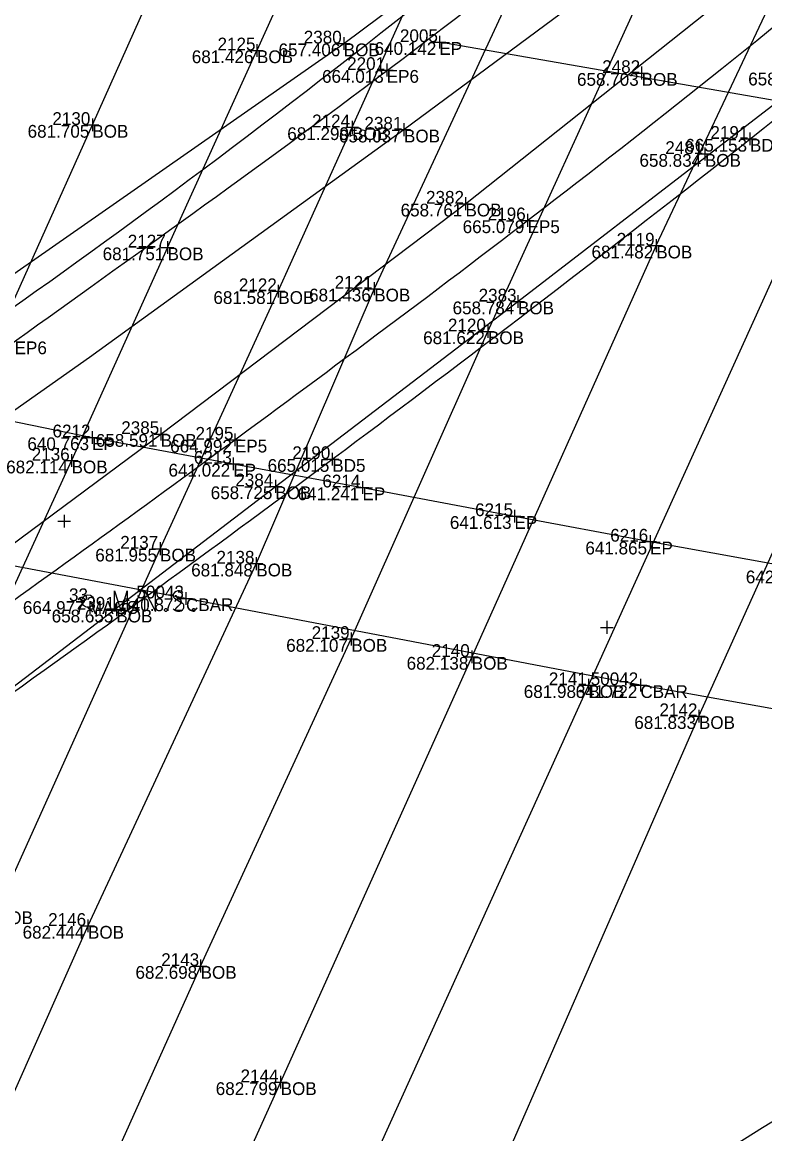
# Model space of a CAD drawing. Extents: x 2197382 to 2204062, y 634117 to 636522.
# Drawn here: x 2202695.7 to 2202753.9, y 635314.3 to 635401.4 of the extents above; entities that cross this region are included whole.
import ezdxf

# ---------------------------------------------------------------- set-up
doc = ezdxf.new("R2010")
doc.units = 0
for name, color, linetype in [('_CIVIL_CONSTRUCTION', 7, 'Continuous'), ('BR_X_SV_Bottom_of_Beam', 7, 'Continuous'), ('BR_X_SV_Bottom_of_Beam_Text', 7, 'Continuous'), ('BR_X_SV_Deck_Top', 7, 'Continuous'), ('BR_X_SV_Deck_Top_Text', 7, 'Continuous'), ('GE_P_Alignment_100_Distances', 7, 'Continuous'), ('RD_X_Concrete_Barrier', 7, 'Continuous'), ('SH_Border', 7, 'Continuous'), ('SH_Cut_Line', 7, 'Continuous'), ('SH_Data', 7, 'Continuous'), ('SV_P_Control_Cells_Set', 7, 'Continuous')]:
    doc.layers.add(name, color=color, linetype=linetype)

msp = doc.modelspace()

# ---------------------------------------------------------------- linework, layer by layer
at = {"layer": '_CIVIL_CONSTRUCTION'}
for p, q in [((2202720.902, 635400.269), (2202720.902, 635399.269)), ((2202728.393, 635400.378), (2202728.393, 635399.378)), ((2202713.604, 635399.229), (2202714.604, 635399.229)), ((2202714.104, 635399.729), (2202714.104, 635398.729)), ((2202714.104, 635399.229), (2202714.104, 635399.229)), ((2202720.402, 635399.769), (2202721.402, 635399.769)), ((2202720.902, 635399.769), (2202720.902, 635399.769)), ((2202727.893, 635399.878), (2202728.893, 635399.878)), ((2202728.393, 635399.878), (2202728.393, 635399.878)), ((2202723.767, 635397.691), (2202724.767, 635397.691)), ((2202724.267, 635398.191), (2202724.267, 635397.191)), ((2202724.267, 635397.691), (2202724.267, 635397.691)), ((2202743.737, 635397.455), (2202744.737, 635397.455)), ((2202744.237, 635397.955), (2202744.237, 635396.955)), ((2202744.237, 635397.455), (2202744.237, 635397.455)), ((2202701.21, 635393.885), (2202701.21, 635392.885)), ((2202700.71, 635393.385), (2202701.71, 635393.385)), ((2202701.21, 635393.385), (2202701.21, 635393.385)), ((2202721.062, 635393.2), (2202722.062, 635393.2)), ((2202721.562, 635393.7), (2202721.562, 635392.7)), ((2202721.562, 635393.2), (2202721.562, 635393.2)), ((2202725.122, 635393.015), (2202726.122, 635393.015)), ((2202725.622, 635393.515), (2202725.622, 635392.515)), ((2202725.622, 635393.015), (2202725.622, 635393.015)), ((2202752.224, 635392.292), (2202753.224, 635392.292)), ((2202752.724, 635392.792), (2202752.724, 635391.792)), ((2202752.724, 635392.292), (2202752.724, 635392.292)), ((2202749.19, 635391.608), (2202749.19, 635390.608)), ((2202748.69, 635391.108), (2202749.69, 635391.108)), ((2202749.19, 635391.108), (2202749.19, 635391.108)), ((2202729.939, 635387.213), (2202730.939, 635387.213)), ((2202730.439, 635387.713), (2202730.439, 635386.713)), ((2202730.439, 635387.213), (2202730.439, 635387.213)), ((2202735.303, 635386.407), (2202735.303, 635385.407)), ((2202734.803, 635385.907), (2202735.803, 635385.907)), ((2202735.303, 635385.907), (2202735.303, 635385.907)), ((2202707.099, 635384.278), (2202707.099, 635383.278)), ((2202745.383, 635384.423), (2202745.383, 635383.423)), ((2202706.599, 635383.778), (2202707.599, 635383.778)), ((2202707.099, 635383.778), (2202707.099, 635383.778)), ((2202744.883, 635383.923), (2202745.883, 635383.923)), ((2202745.383, 635383.923), (2202745.383, 635383.923)), ((2202715.777, 635380.853), (2202715.777, 635379.853)), ((2202723.291, 635381.051), (2202723.291, 635380.051)), ((2202715.277, 635380.353), (2202716.277, 635380.353)), ((2202715.777, 635380.353), (2202715.777, 635380.353)), ((2202722.791, 635380.551), (2202723.791, 635380.551)), ((2202723.291, 635380.551), (2202723.291, 635380.551)), ((2202734.551, 635380.043), (2202734.551, 635379.043)), ((2202734.051, 635379.543), (2202735.051, 635379.543)), ((2202734.551, 635379.543), (2202734.551, 635379.543)), ((2202732.197, 635377.703), (2202732.197, 635376.703)), ((2202731.697, 635377.203), (2202732.697, 635377.203)), ((2202732.197, 635377.203), (2202732.197, 635377.203)), ((2202706.563, 635369.657), (2202706.563, 635368.657)), ((2202700.684, 635368.894), (2202701.684, 635368.894)), ((2202701.184, 635369.394), (2202701.184, 635368.394)), ((2202701.184, 635368.894), (2202701.184, 635368.894)), ((2202706.063, 635369.157), (2202707.063, 635369.157)), ((2202706.563, 635369.157), (2202706.563, 635369.157)), ((2202711.879, 635368.711), (2202712.879, 635368.711)), ((2202712.379, 635369.211), (2202712.379, 635368.211)), ((2202712.379, 635368.711), (2202712.379, 635368.711)), ((2202699.084, 635367.074), (2202700.084, 635367.074)), ((2202699.584, 635367.574), (2202699.584, 635366.574)), ((2202699.584, 635367.074), (2202699.584, 635367.074)), ((2202712.248, 635367.324), (2202712.248, 635366.324)), ((2202719.509, 635367.194), (2202720.509, 635367.194)), ((2202720.009, 635367.694), (2202720.009, 635366.694)), ((2202720.009, 635367.194), (2202720.009, 635367.194)), ((2202711.748, 635366.824), (2202712.748, 635366.824)), ((2202712.248, 635366.824), (2202712.248, 635366.824)), ((2202715.55, 635365.554), (2202715.55, 635364.554)), ((2202722.37, 635365.473), (2202722.37, 635364.473)), ((2202715.05, 635365.054), (2202716.05, 635365.054)), ((2202715.55, 635365.054), (2202715.55, 635365.054)), ((2202721.87, 635364.973), (2202722.87, 635364.973)), ((2202722.37, 635364.973), (2202722.37, 635364.973)), ((2202699.008, 635362.818), (2202699.008, 635361.818)), ((2202733.779, 635362.722), (2202734.779, 635362.722)), ((2202734.279, 635363.222), (2202734.279, 635362.222)), ((2202734.279, 635362.722), (2202734.279, 635362.722)), ((2202698.508, 635362.318), (2202699.508, 635362.318)), ((2202699.008, 635362.318), (2202699.008, 635362.318)), ((2202744.899, 635361.221), (2202744.899, 635360.221)), ((2202706.01, 635360.169), (2202707.01, 635360.169)), ((2202706.51, 635360.669), (2202706.51, 635359.669)), ((2202706.51, 635360.169), (2202706.51, 635360.169)), ((2202744.399, 635360.721), (2202745.399, 635360.721)), ((2202744.899, 635360.721), (2202744.899, 635360.721)), ((2202713.553, 635358.998), (2202714.553, 635358.998)), ((2202714.053, 635359.498), (2202714.053, 635358.498)), ((2202714.053, 635358.998), (2202714.053, 635358.998)), ((2202708.544, 635356.774), (2202708.544, 635355.774)), ((2202703.092, 635355.89), (2202703.092, 635354.89)), ((2202708.044, 635356.274), (2202709.044, 635356.274)), ((2202708.544, 635356.274), (2202708.544, 635356.274)), ((2202702.592, 635355.39), (2202703.592, 635355.39)), ((2202703.092, 635355.39), (2202703.092, 635355.39)), ((2202741.009, 635354.004), (2202742.009, 635354.004)), ((2202741.509, 635354.504), (2202741.509, 635353.504)), ((2202741.509, 635354.004), (2202741.509, 635354.004)), ((2202720.992, 635353.092), (2202721.992, 635353.092)), ((2202721.492, 635353.592), (2202721.492, 635352.592)), ((2202721.492, 635353.092), (2202721.492, 635353.092)), ((2202730.929, 635352.186), (2202730.929, 635351.186)), ((2202730.429, 635351.686), (2202731.429, 635351.686)), ((2202730.929, 635351.686), (2202730.929, 635351.686)), ((2202739.569, 635349.468), (2202740.569, 635349.468)), ((2202740.069, 635349.968), (2202740.069, 635348.968)), ((2202740.069, 635349.468), (2202740.069, 635349.468)), ((2202743.64, 635349.469), (2202744.64, 635349.469)), ((2202744.14, 635349.969), (2202744.14, 635348.969)), ((2202744.14, 635349.469), (2202744.14, 635349.469)), ((2202748.226, 635347.039), (2202749.226, 635347.039)), ((2202748.726, 635347.539), (2202748.726, 635346.539)), ((2202748.726, 635347.039), (2202748.726, 635347.039)), ((2202700.37, 635330.601), (2202701.37, 635330.601)), ((2202700.87, 635331.101), (2202700.87, 635330.101)), ((2202700.87, 635330.601), (2202700.87, 635330.601)), ((2202709.688, 635327.957), (2202709.688, 635326.957)), ((2202709.188, 635327.457), (2202710.188, 635327.457)), ((2202709.688, 635327.457), (2202709.688, 635327.457)), ((2202715.46, 635318.345), (2202716.46, 635318.345)), ((2202715.96, 635318.845), (2202715.96, 635317.845)), ((2202715.96, 635318.345), (2202715.96, 635318.345))]:
    msp.add_line(p, q, dxfattribs=at)
at = {"layer": 'BR_X_SV_Bottom_of_Beam'}
for p, q in [((2202729.172, 635432.784), (2202714.104, 635399.229)), ((2202721.562, 635393.2), (2202737.494, 635428.47)), ((2202745.383, 635383.923), (2202761.441, 635418.052)), ((2202732.197, 635377.203), (2202748.335, 635412.641)), ((2202737.812, 635411.851), (2202723.291, 635380.551)), ((2202707.099, 635383.778), (2202714.104, 635399.229)), ((2202748.726, 635347.039), (2202772.072, 635399.002)), ((2202715.777, 635380.353), (2202721.562, 635393.2)), ((2202758.945, 635391.176), (2202740.069, 635349.468)), ((2202707.099, 635383.778), (2202699.584, 635367.074)), ((2202745.383, 635383.923), (2202730.929, 635351.686)), ((2202706.51, 635360.169), (2202715.777, 635380.353)), ((2202723.291, 635380.551), (2202714.053, 635358.998)), ((2202721.492, 635353.092), (2202732.197, 635377.203)), ((2202699.584, 635367.074), (2202684.722, 635334.745)), ((2202693.73, 635331.743), (2202706.51, 635360.169)), ((2202714.053, 635358.998), (2202700.87, 635330.601)), ((2202709.688, 635327.457), (2202721.492, 635353.092)), ((2202730.929, 635351.686), (2202715.96, 635318.345)), ((2202729.105, 635302.144), (2202748.726, 635347.039))]:
    msp.add_line(p, q, dxfattribs=at)
for points in [[(2202550.738, 635261.3), (2202572.992, 635273.891), (2202594.556, 635285.879), (2202604.099, 635291.315), (2202615.232, 635297.565), (2202632.636, 635308.407), (2202649.916, 635319.32), (2202686.545, 635342.9), (2202715.55, 635365.054), (2202734.551, 635379.543), (2202765.2, 635403.192), (2202782.887, 635418.269), (2202797.351, 635430.625), (2202810.639, 635442.162), (2202822.488, 635452.15)], [(2202692.588, 635374.159), (2202701.21, 635393.385), (2202709.973, 635412.997), (2202724.495, 635444.824)], [(2202692.151, 635358.452), (2202706.563, 635369.157), (2202730.439, 635387.213), (2202776.237, 635423.633), (2202788.518, 635433.729)], [(2202513.324, 635270.745), (2202518.461, 635273.222), (2202532.26, 635280.283), (2202548.237, 635288.645), (2202560.651, 635295.117), (2202588.283, 635310.399), (2202608.693, 635322.992), (2202620.515, 635330.213), (2202626.072, 635333.707), (2202636.254, 635340.133), (2202656.933, 635353.888), (2202662.455, 635358.969), (2202720.902, 635399.769), (2202735.154, 635410.438), (2202760.7, 635432.077)], [(2202624.848, 635323.108), (2202626.632, 635325.163), (2202640.898, 635333.252), (2202660.713, 635346.321), (2202681.445, 635361.418), (2202700.993, 635375.17), (2202725.622, 635393.015), (2202741.163, 635404.571), (2202768.027, 635427.422)], [(2202740.069, 635349.468), (2202715.953, 635296.202), (2202694.386, 635248.414), (2202667.266, 635188.144), (2202637.877, 635121.952)], [(2202700.87, 635330.601), (2202688.972, 635303.876), (2202667.875, 635257.009), (2202653.513, 635225.855), (2202612.344, 635134.534)], [(2202709.688, 635327.457), (2202697.509, 635300.34), (2202676.043, 635253.072), (2202658.006, 635212.414), (2202623.889, 635137.034)], [(2202715.96, 635318.345), (2202706.84, 635298.156), (2202685.056, 635250.63), (2202665.977, 635208.006), (2202633.465, 635136.302)]]:
    msp.add_lwpolyline(points, dxfattribs=at)
at = {"layer": 'BR_X_SV_Deck_Top'}
for points in [[(2202430.051, 635233.588), (2202439.74, 635238.507), (2202466.339, 635247.691), (2202507.168, 635268.028), (2202543.723, 635286.397), (2202574.877, 635303.715), (2202604.911, 635320.157), (2202634.127, 635339.4), (2202663.018, 635358.594), (2202692.445, 635376.507), (2202729.246, 635404.451), (2202755.806, 635426.417), (2202769.739, 635438.84)], [(2202458.051, 635216.681), (2202477.116, 635219.979), (2202511.723, 635243.78), (2202554.955, 635262.299), (2202588.014, 635280.674), (2202608.342, 635292.387), (2202640.833, 635312.137), (2202668.147, 635329.948), (2202698.573, 635351.315), (2202722.135, 635368.649), (2202754.604, 635393.426), (2202777.494, 635412.293), (2202789.607, 635422.635)], [(2202895.365, 635391.811), (2202885.347, 635387.334), (2202865.192, 635377.205), (2202839.037, 635363.762), (2202813.103, 635349.723), (2202789.18, 635336.138), (2202762.388, 635320.287), (2202740.668, 635306.565), (2202716.628, 635290.831), (2202693.394, 635275.343), (2202664.567, 635254.787), (2202633.536, 635231.765), (2202595.89, 635201.643), (2202569.397, 635178.622), (2202555.165, 635165.675)], [(2202923.181, 635376.197), (2202906.167, 635369.085), (2202881.487, 635355.934), (2202846.739, 635338.13), (2202819.013, 635322.649), (2202790.142, 635306.09), (2202754.022, 635283.778), (2202709.422, 635255.583), (2202663.285, 635220.884), (2202620.566, 635187.914), (2202595.285, 635167.396), (2202582.509, 635156.81)]]:
    msp.add_open_spline(points, degree=3, dxfattribs=at)
at = {"layer": 'GE_P_Alignment_100_Distances'}
for points in [[(2202975.789, 635361.358), (2202911.398, 635369.868), (2202894.289, 635372.201), (2202871.103, 635375.635), (2202823.555, 635383.286), (2202728.393, 635399.878)], [(2202624.529, 635384.858), (2202633.951, 635382.782), (2202644.483, 635380.376), (2202656.846, 635378.03), (2202666.311, 635376.086), (2202679.647, 635373.315), (2202690.616, 635371.05), (2202701.184, 635368.894), (2202712.248, 635366.824), (2202722.37, 635364.973), (2202734.279, 635362.722), (2202744.899, 635360.721), (2202757.462, 635358.453), (2202767.225, 635356.724), (2202777.62, 635355.092), (2202788.795, 635353.014), (2202801.805, 635351.004), (2202818.285, 635348.253), (2202834.346, 635345.79)]]:
    msp.add_lwpolyline(points, dxfattribs=at)
for points in [[(2202483.163, 635252.761), (2202495.402, 635258.227), (2202515.209, 635267.824), (2202539.505, 635280.183), (2202556.272, 635289.074), (2202570.794, 635297.089), (2202585.76, 635305.335), (2202607.83, 635319.01), (2202630.778, 635332.646), (2202656.431, 635348.815), (2202675.69, 635362.468), (2202698.981, 635379.185), (2202729.904, 635401.353), (2202753.674, 635420.874), (2202767.823, 635433.185)], [(2202457.668, 635223.282), (2202466.48, 635226.872), (2202500.455, 635242.355), (2202539.476, 635261.183), (2202573.06, 635279.52), (2202585.609, 635286.631), (2202599.84, 635294.842), (2202617.618, 635305.231), (2202642.294, 635320.395), (2202667.372, 635336.77), (2202691.723, 635353.633), (2202713.413, 635369.403), (2202739.641, 635388.973), (2202758.657, 635404.276), (2202770.061, 635413.813)], [(2202926.993, 635398.223), (2202911.054, 635391.267), (2202884.78, 635379.221), (2202850.251, 635362.173), (2202828.215, 635350.038), (2202808.09, 635339.198), (2202790.855, 635329.045), (2202764, 635313.325), (2202738.781, 635297.635), (2202713.051, 635280.577), (2202697.019, 635269.602), (2202684.529, 635260.864), (2202668.986, 635249.754), (2202642.65, 635230.806), (2202596.561, 635193.887), (2202560.681, 635163.156), (2202538.312, 635142.813)], [(2202919.499, 635378.368), (2202901.447, 635370.678), (2202875.936, 635356.879), (2202844.592, 635341.598), (2202825.856, 635330.823), (2202809.466, 635322.019), (2202780.051, 635304.409), (2202746.062, 635282.999), (2202707.717, 635258.176), (2202682.244, 635240.209), (2202658.947, 635222.257), (2202614.143, 635189.251), (2202577.354, 635157.516), (2202549.508, 635131.427)]]:
    msp.add_open_spline(points, degree=3, dxfattribs=at)
at = {"layer": 'RD_X_Concrete_Barrier'}
msp.add_lwpolyline([(2202800.07, 635339.72), (2202776.238, 635343.723), (2202744.14, 635349.469), (2202708.544, 635356.274), (2202679.329, 635361.788), (2202653.683, 635367.051)], dxfattribs=at)
at = {"layer": 'SV_P_Control_Cells_Set'}
for points in [[(2202702.958, 635355.258), (2202702.958, 635356.858), (2202703.465, 635355.258), (2202703.95, 635356.858), (2202703.95, 635355.258)], [(2202705.328, 635355.258), (2202705.328, 635356.858), (2202706.155, 635355.258), (2202706.155, 635356.858)], [(2202708.305, 635356.745), (2202708.283, 635356.77), (2202708.249, 635356.795), (2202708.15, 635356.833), (2202708.029, 635356.858), (2202707.941, 635356.858), (2202707.908, 635356.858), (2202707.764, 635356.821), (2202707.643, 635356.745), (2202707.566, 635356.644), (2202707.544, 635356.543), (2202707.544, 635356.468), (2202707.566, 635356.367), (2202707.654, 635356.279), (2202708.261, 635355.901), (2202708.316, 635355.851), (2202708.338, 635355.8), (2202708.36, 635355.725), (2202708.36, 635355.649), (2202708.349, 635355.573), (2202708.338, 635355.523), (2202708.316, 635355.46), (2202708.294, 635355.41), (2202708.271, 635355.372), (2202708.238, 635355.334), (2202708.205, 635355.309), (2202708.161, 635355.284), (2202708.128, 635355.271), (2202708.029, 635355.258), (2202707.875, 635355.258), (2202707.776, 635355.284), (2202707.632, 635355.372), (2202707.544, 635355.447)], [(2202704.722, 635355.473), (2202704.777, 635355.473), (2202704.81, 635355.447), (2202704.843, 635355.397), (2202704.843, 635355.334), (2202704.81, 635355.284), (2202704.777, 635355.258), (2202704.722, 635355.258), (2202704.689, 635355.284), (2202704.656, 635355.334), (2202704.656, 635355.397), (2202704.689, 635355.447), (2202704.722, 635355.473)], [(2202706.938, 635355.473), (2202706.993, 635355.473), (2202707.026, 635355.447), (2202707.059, 635355.397), (2202707.059, 635355.334), (2202707.026, 635355.284), (2202706.993, 635355.258), (2202706.938, 635355.258), (2202706.905, 635355.284), (2202706.872, 635355.334), (2202706.872, 635355.397), (2202706.905, 635355.447), (2202706.938, 635355.473)], [(2202709.12, 635355.473), (2202709.175, 635355.473), (2202709.209, 635355.447), (2202709.241, 635355.397), (2202709.241, 635355.334), (2202709.209, 635355.284), (2202709.175, 635355.258), (2202709.12, 635355.258), (2202709.087, 635355.284), (2202709.054, 635355.334), (2202709.054, 635355.397), (2202709.087, 635355.447), (2202709.12, 635355.473)]]:
    msp.add_lwpolyline(points, dxfattribs=at)
msp.add_circle((2202700.868, 635356.058), 0.497, dxfattribs=at)

# ---------------------------------------------------------------- texts
at = {"layer": 'BR_X_SV_Bottom_of_Beam_Text'}
for s, p in [('2125', (2202711.015, 635399.229)), ('2380', (2202717.77, 635399.769)), ('681.426', (2202709, 635398.229)), ('BOB', (2202714.104, 635398.229)), ('657.406', (2202715.798, 635398.769)), ('BOB', (2202720.902, 635398.769)), ('2482', (2202741.145, 635397.455)), ('658.703', (2202739.173, 635396.455)), ('BOB', (2202744.237, 635396.455)), ('658.862', (2202752.586, 635396.485)), ('2130', (2202698.078, 635393.385)), ('2124', (2202718.421, 635393.2)), ('2381', (2202722.522, 635393.015)), ('681.705', (2202696.14, 635392.385)), ('BOB', (2202701.21, 635392.385)), ('681.299', (2202716.478, 635392.2)), ('658.037', (2202720.526, 635392.015)), ('BOB', (2202721.562, 635392.2)), ('BOB', (2202725.622, 635392.015)), ('2481', (2202746.09, 635391.108)), ('658.834', (2202744.068, 635390.108)), ('BOB', (2202749.19, 635390.108)), ('2382', (2202727.347, 635387.213)), ('658.761', (2202725.357, 635386.213)), ('BOB', (2202730.439, 635386.213)), ('2127', (2202703.984, 635383.778)), ('2119', (2202742.281, 635383.923)), ('681.751', (2202702.017, 635382.778)), ('BOB', (2202707.099, 635382.778)), ('681.482', (2202740.31, 635382.923)), ('BOB', (2202745.383, 635382.923)), ('2122', (2202712.685, 635380.353)), ('2121', (2202720.191, 635380.551)), ('681.581', (2202710.695, 635379.353)), ('BOB', (2202715.777, 635379.353)), ('681.436', (2202718.187, 635379.551)), ('BOB', (2202723.291, 635379.551)), ('2383', (2202731.468, 635379.543)), ('658.784', (2202729.429, 635378.543)), ('BOB', (2202734.551, 635378.543)), ('2120', (2202729.065, 635377.203)), ('681.622', (2202727.124, 635376.203)), ('BOB', (2202732.197, 635376.203)), ('2385', (2202703.474, 635369.157)), ('658.591', (2202701.481, 635368.157)), ('BOB', (2202706.563, 635368.157)), ('2136', (2202696.461, 635367.074)), ('682.114', (2202694.462, 635366.074)), ('BOB', (2202699.584, 635366.074)), ('2384', (2202712.409, 635365.054)), ('658.725', (2202710.48, 635364.054)), ('BOB', (2202715.55, 635364.054)), ('2137', (2202703.395, 635360.169)), ('681.955', (2202701.44, 635359.169)), ('BOB', (2202706.51, 635359.169)), ('2138', (2202710.934, 635358.998)), ('681.848', (2202708.953, 635357.998)), ('BOB', (2202714.053, 635357.998)), ('2391', (2202699.992, 635355.39)), ('658.655', (2202698.022, 635354.39)), ('BOB', (2202703.092, 635354.39)), ('2139', (2202718.39, 635353.092)), ('682.107', (2202716.396, 635352.092)), ('BOB', (2202721.492, 635352.092)), ('2140', (2202727.797, 635351.686)), ('682.138', (2202725.829, 635350.686)), ('BOB', (2202730.929, 635350.686)), ('2141', (2202736.969, 635349.468)), ('681.983', (2202735.005, 635348.468)), ('BOB', (2202740.069, 635348.468)), ('2142', (2202745.634, 635347.039)), ('681.833', (2202743.662, 635346.039)), ('BOB', (2202748.726, 635346.039)), ('BOB', (2202693.73, 635330.743)), ('2146', (2202697.747, 635330.601)), ('682.444', (2202695.748, 635329.601)), ('BOB', (2202700.87, 635329.601)), ('2143', (2202706.605, 635327.457)), ('682.698', (2202704.588, 635326.457)), ('BOB', (2202709.688, 635326.457)), ('2144', (2202712.819, 635318.345)), ('682.799', (2202710.876, 635317.345)), ('BOB', (2202715.96, 635317.345))]:
    msp.add_text(s, height=1, dxfattribs=at).set_placement(p)
at = {"layer": 'BR_X_SV_Deck_Top_Text'}
for s, p in [('2191', (2202749.624, 635392.292)), ('665.153', (2202747.66, 635391.292)), ('BD5', (2202752.724, 635391.292)), ('2190', (2202716.877, 635367.194)), ('665.015', (2202714.939, 635366.194)), ('BD5', (2202720.009, 635366.194))]:
    msp.add_text(s, height=1, dxfattribs=at).set_placement(p)
at = {"layer": 'SH_Border'}
for s, p in [('EP', (2202728.393, 635398.878)), ('EP6', (2202724.267, 635396.691)), ('EP5', (2202735.303, 635384.907)), ('EP6', (2202695.123, 635375.414)), ('EP', (2202701.184, 635367.894)), ('EP5', (2202712.379, 635367.711)), ('EP', (2202712.248, 635365.824)), ('EP', (2202722.37, 635363.973)), ('EP', (2202734.279, 635361.722)), ('EP', (2202744.899, 635359.721)), ('MAGS', (2202700.868, 635355.059)), ('CBAR', (2202708.544, 635355.274)), ('CBAR', (2202744.14, 635348.469))]:
    msp.add_text(s, height=1, dxfattribs=at).set_placement(p)
at = {"layer": 'SH_Cut_Line'}
for s, p in [('2005', (2202725.304, 635399.878)), ('2201', (2202721.167, 635397.691)), ('2196', (2202732.18, 635385.907)), ('6212', (2202698.092, 635368.894)), ('2195', (2202709.29, 635368.711)), ('6213', (2202709.165, 635366.824)), ('6214', (2202719.229, 635364.973)), ('6215', (2202731.19, 635362.722)), ('6216', (2202741.776, 635360.721)), ('50043', (2202704.663, 635356.274)), ('33', (2202699.382, 635356.059)), ('50042', (2202740.25, 635349.469))]:
    msp.add_text(s, height=1, dxfattribs=at).set_placement(p)
at = {"layer": 'SH_Data'}
for s, p in [('640.142', (2202723.32, 635398.878)), ('664.013', (2202719.203, 635396.691)), ('665.079', (2202730.219, 635384.907)), ('640.763', (2202696.12, 635367.894)), ('664.992', (2202707.306, 635367.711)), ('641.022', (2202707.175, 635365.824)), ('641.241', (2202717.288, 635363.973)), ('641.613', (2202729.215, 635361.722)), ('641.865', (2202739.829, 635359.721)), ('642.203', (2202752.398, 635357.453)), ('664.977', (2202695.772, 635355.059)), ('640.872', (2202703.471, 635355.274)), ('641.722', (2202739.067, 635348.469))]:
    msp.add_text(s, height=1, dxfattribs=at).set_placement(p)

doc.saveas('drawing.dxf')
